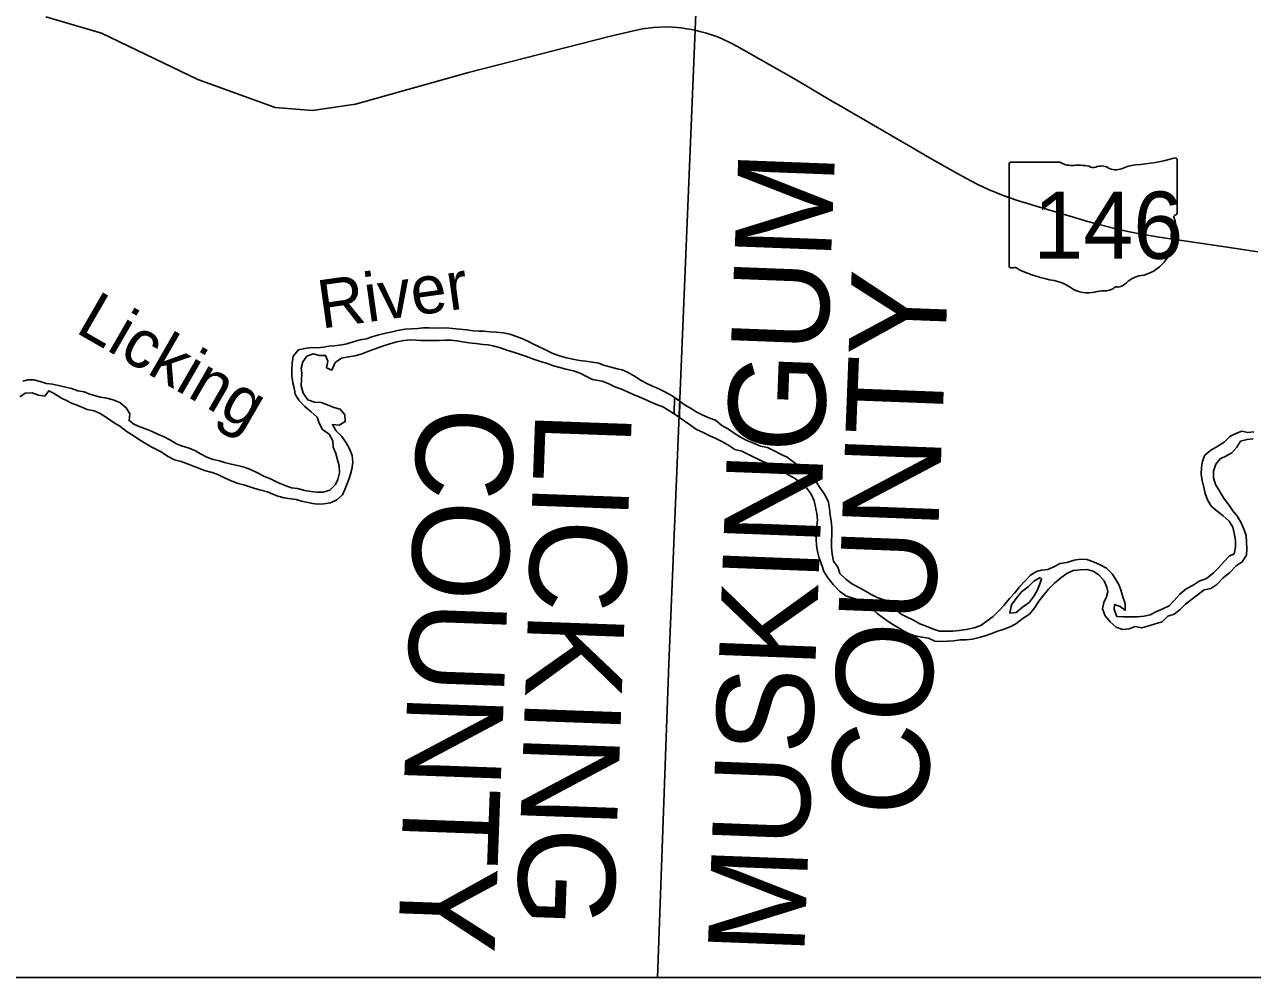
# Model space of a CAD drawing. Extents: x 0 to 34, y 0 to 22.
# Drawn here: x 13.652 to 17.715, y 13.067 to 16.221 of the extents above; entities that cross this region are included whole.
import ezdxf

# ---------------------------------------------------------------- set-up
doc = ezdxf.new("R2010")
doc.units = 0
for name, color, linetype in [('GM_X_County', 7, 'Continuous'), ('GM_X_County_Text', 7, 'Continuous'), ('GM_X_Major_River', 7, 'Continuous'), ('GM_X_Major_River_Text', 7, 'Continuous'), ('GM_X_State_Route', 7, 'Continuous'), ('GM_X_State_Shield', 7, 'Continuous'), ('SH_Text', 7, 'Continuous')]:
    doc.layers.add(name, color=color, linetype=linetype)

msp = doc.modelspace()

# ---------------------------------------------------------------- linework, layer by layer
at = {"layer": 'GM_X_County'}
msp.add_lwpolyline([(15.7461, 13.067), (15.7838, 14.1047), (15.8705, 16.2037), (15.9482, 18.1471), (15.9491, 18.1833), (15.9623, 18.562), (15.9755, 18.686), (15.9829, 18.8439), (16.0536, 20.907)], dxfattribs=at)
at = {"layer": 'GM_X_Major_River'}
for p, q in [((15.801, 14.9327), (15.8031, 14.987)), ((15.8186, 14.9217), (15.8206, 14.9754))]:
    msp.add_line(p, q, dxfattribs=at)
for points in [[(14.8859, 15.2086), (14.8681, 15.2047), (14.847, 15.2001), (14.8246, 15.1943), (14.8004, 15.1877), (14.7832, 15.1806), (14.7621, 15.1773), (14.7391, 15.1714), (14.718, 15.1643), (14.7014, 15.161), (14.6765, 15.1577), (14.6586, 15.1563), (14.6407, 15.1537), (14.6209, 15.1517), (14.6024, 15.1528), (14.5794, 15.1495), (14.5577, 15.145), (14.5405, 15.1237), (14.5368, 15.1001), (14.5362, 15.0789), (14.5363, 15.0585), (14.5396, 15.0354), (14.5442, 15.0188), (14.5475, 14.9977), (14.5591, 14.9779), (14.579, 14.9569), (14.6001, 14.9391), (14.62, 14.9213), (14.6271, 14.9015), (14.6375, 14.8804), (14.6593, 14.8658), (14.6715, 14.8435), (14.6735, 14.823), (14.6813, 14.8019), (14.6878, 14.7809), (14.693, 14.7604), (14.6943, 14.738), (14.688, 14.7149), (14.6811, 14.6989), (14.662, 14.6803), (14.6403, 14.6738), (14.6198, 14.6736), (14.6006, 14.6755), (14.5789, 14.6792), (14.5552, 14.6855), (14.5354, 14.6879), (14.5136, 14.6955), (14.4919, 14.7044), (14.4682, 14.7164), (14.4438, 14.7265), (14.4227, 14.7379), (14.3996, 14.7487), (14.3785, 14.7563), (14.3567, 14.7613), (14.3356, 14.7663), (14.3132, 14.772), (14.2972, 14.777), (14.2761, 14.782), (14.255, 14.7889), (14.2339, 14.8004), (14.2172, 14.8099), (14.1961, 14.8187), (14.1711, 14.8269), (14.1545, 14.8339), (14.1327, 14.8466), (14.1115, 14.8573), (14.0949, 14.8643), (14.0737, 14.8744), (14.052, 14.8826), (14.0334, 14.8902), (14.0136, 14.8991), (13.9975, 14.9105), (14, 14.9323), (13.9877, 14.9527), (13.9666, 14.9699), (13.9448, 14.9794), (13.9243, 14.985), (13.9026, 14.9881), (13.886, 14.9919), (13.8648, 14.9995), (13.8488, 15.0051), (13.8284, 15.0089), (13.8066, 15.0171), (13.7644, 15.0271), (13.7439, 15.0315), (13.7228, 15.0333), (13.7029, 15.0396), (13.6825, 15.0453), (13.662, 15.0452), (13.6454, 15.0406)], [(15.8206, 14.9754), (15.7932, 14.9937), (15.7708, 15.0051), (15.7509, 15.0159), (15.7298, 15.0247), (15.7132, 15.0323), (15.692, 15.0431), (15.6702, 15.0577), (15.6465, 15.0704), (15.6292, 15.078), (15.6132, 15.0817), (15.5889, 15.088), (15.5678, 15.0937), (15.5518, 15.1), (15.5307, 15.1043), (15.5083, 15.1068), (15.4878, 15.1099), (15.4661, 15.1143), (15.445, 15.118), (15.4219, 15.1249), (15.3995, 15.1325), (15.3752, 15.1445), (15.3528, 15.1559), (15.3361, 15.1635), (15.3194, 15.1724), (15.297, 15.1819), (15.2798, 15.1888), (15.2573, 15.1964), (15.2356, 15.2008), (15.2126, 15.2032), (15.1921, 15.2044), (15.1717, 15.2062), (15.155, 15.2068), (15.1371, 15.2073), (15.1141, 15.2111), (15.0917, 15.2135), (15.0694, 15.2153), (15.0476, 15.2171), (15.008, 15.2169), (14.9907, 15.2175), (14.9709, 15.218), (14.953, 15.2154), (14.9319, 15.2146), (14.9108, 15.2126), (14.8859, 15.2086)], [(14.7655, 15.1306), (14.7872, 15.139), (14.8121, 15.1481), (14.8331, 15.1553), (14.8606, 15.1644), (14.8835, 15.1709), (14.9072, 15.1755), (14.9289, 15.1775), (14.9468, 15.1763), (14.9628, 15.1751), (14.9852, 15.1752), (15.0075, 15.176), (15.0241, 15.1761), (15.0452, 15.1768), (15.0612, 15.1762), (15.0836, 15.1744), (15.1009, 15.1713), (15.122, 15.1682), (15.1444, 15.1651), (15.1693, 15.1627), (15.1859, 15.1615), (15.2019, 15.1577), (15.2262, 15.1515), (15.2474, 15.1433), (15.273, 15.1357), (15.2966, 15.1281), (15.3133, 15.1231), (15.3363, 15.1136), (15.3626, 15.1054), (15.3786, 15.1004), (15.4016, 15.0922), (15.4234, 15.0859), (15.4426, 15.0809), (15.4682, 15.0746), (15.4925, 15.0664), (15.5091, 15.0575), (15.5309, 15.0468), (15.5629, 15.0405), (15.5834, 15.0336), (15.6052, 15.0222), (15.6269, 15.0146), (15.6474, 15.0051), (15.6635, 14.9975), (15.6878, 14.988), (15.7038, 14.9811), (15.7275, 14.9703), (15.7435, 14.964), (15.764, 14.9558), (15.7839, 14.9437), (15.8186, 14.9217)], [(13.636, 14.9887), (13.6539, 15.001), (13.6763, 15.0024), (13.6974, 14.9942), (13.7185, 14.9911), (13.7318, 15.009), (13.7479, 15.0014), (13.7741, 14.9849), (13.7908, 14.9767), (13.8068, 14.9678), (13.8228, 14.9621), (13.8414, 14.9552), (13.8587, 14.947), (13.8817, 14.9426), (13.9022, 14.9337), (13.9265, 14.9185), (13.9477, 14.9026), (13.9669, 14.8918), (13.9907, 14.8727), (14.0112, 14.8607), (14.0323, 14.8467), (14.0483, 14.8372), (14.0701, 14.8232), (14.0881, 14.8144), (14.1041, 14.8074), (14.1252, 14.7928), (14.1483, 14.7807), (14.1694, 14.7751), (14.1912, 14.7675), (14.2072, 14.7605), (14.2251, 14.7542), (14.2469, 14.7454), (14.2725, 14.7385), (14.291, 14.7315), (14.3128, 14.7208), (14.3352, 14.7113), (14.3589, 14.7024), (14.3768, 14.698), (14.3967, 14.6911), (14.414, 14.6854), (14.4332, 14.6798), (14.4556, 14.6741), (14.4735, 14.6665), (14.4895, 14.6608), (14.5113, 14.6552), (14.533, 14.6515), (14.5503, 14.6496), (14.5682, 14.644), (14.5893, 14.6396), (14.6053, 14.6358), (14.6213, 14.634), (14.6417, 14.6347), (14.6641, 14.6387), (14.6851, 14.6484), (14.7042, 14.6645), (14.7118, 14.6818), (14.72, 14.7042), (14.7283, 14.7254), (14.7352, 14.7491), (14.7383, 14.7728), (14.7363, 14.7945), (14.7279, 14.815), (14.7163, 14.8373), (14.7015, 14.8583), (14.6816, 14.8781), (14.6706, 14.8972), (14.6924, 14.8954), (14.7128, 14.907), (14.712, 14.9294), (14.6966, 14.9485), (14.6755, 14.9542), (14.6537, 14.9631), (14.6332, 14.9706), (14.6115, 14.9718), (14.5891, 14.9794), (14.5737, 15.0017), (14.5672, 15.0253), (14.5677, 15.0452), (14.5689, 15.0669), (14.5675, 15.0836), (14.5726, 15.1047), (14.5859, 15.124), (14.607, 15.1311), (14.6274, 15.1261), (14.6479, 15.1262), (14.655, 15.107), (14.6513, 15.0853), (14.6686, 15.0777), (14.68, 15.1027), (14.7003, 15.1175), (14.7233, 15.1215), (14.7444, 15.1248), (14.7655, 15.1306)], [(15.8031, 14.987), (15.8382, 14.9614), (15.8581, 14.9501), (15.8747, 14.9399), (15.8946, 14.9291), (15.9164, 14.9196), (15.9388, 14.9114), (15.9593, 14.8942), (15.9811, 14.8815), (16.0003, 14.8688), (16.0208, 14.8561), (16.0425, 14.8447), (16.0643, 14.8352), (16.0874, 14.8257), (16.1104, 14.8219), (16.1322, 14.8099), (16.1533, 14.7991), (16.1751, 14.789), (16.1943, 14.775), (16.2148, 14.7591), (16.2347, 14.7457), (16.2565, 14.7266), (16.2719, 14.7075), (16.2854, 14.6858), (16.3008, 14.6641), (16.3118, 14.6405), (16.3157, 14.6181), (16.3183, 14.5989), (16.3216, 14.5772), (16.323, 14.5561), (16.3237, 14.5343), (16.3219, 14.5119), (16.3226, 14.4908), (16.324, 14.4678), (16.3286, 14.4454), (16.3433, 14.4256), (16.3498, 14.4045), (16.3691, 14.3854), (16.3889, 14.3714), (16.4101, 14.3587), (16.4312, 14.3479), (16.453, 14.3352), (16.4735, 14.3245), (16.4952, 14.3169), (16.5163, 14.3118), (16.5362, 14.2908), (16.551, 14.2704), (16.5721, 14.2596), (16.5933, 14.2495), (16.6144, 14.2374), (16.6355, 14.2298), (16.656, 14.221), (16.6797, 14.2134), (16.7014, 14.2129), (16.7232, 14.2129), (16.7449, 14.2156), (16.7679, 14.2189), (16.7947, 14.2248), (16.8164, 14.2326), (16.8374, 14.2474), (16.8572, 14.2622), (16.8769, 14.2821), (16.8922, 14.2988), (16.9112, 14.3213), (16.9284, 14.3399), (16.9443, 14.3598), (16.9628, 14.3797), (16.9806, 14.399), (17.001, 14.4106), (17.0176, 14.4158), (17.038, 14.4172), (17.0584, 14.4262), (17.0788, 14.4372), (17.1012, 14.4405), (17.1248, 14.4483), (17.1459, 14.4516), (17.1676, 14.4504), (17.1894, 14.4434), (17.2111, 14.4333), (17.2323, 14.4219), (17.2509, 14.4034), (17.2631, 14.3843), (17.2734, 14.3677), (17.2798, 14.3498), (17.2863, 14.3274), (17.2935, 14.3044), (17.2942, 14.2827), (17.2775, 14.2954), (17.2583, 14.3011), (17.2571, 14.2851), (17.2661, 14.2621), (17.2885, 14.2609), (17.3102, 14.2603), (17.3333, 14.2611), (17.3569, 14.2631), (17.3773, 14.267), (17.3977, 14.2786), (17.4188, 14.2871), (17.4392, 14.2974), (17.4557, 14.3147), (17.4735, 14.3346)], [(15.801, 14.9327), (15.8346, 14.9097), (15.8557, 14.895), (15.8756, 14.8811), (15.8974, 14.8709), (15.9192, 14.8595), (15.9396, 14.8513), (15.9588, 14.8417), (15.9793, 14.8303), (16.0018, 14.8151), (16.0254, 14.8088), (16.0479, 14.798), (16.0901, 14.7777), (16.1132, 14.7669), (16.1349, 14.7587), (16.158, 14.746), (16.1791, 14.7314), (16.1996, 14.7193), (16.2195, 14.704), (16.24, 14.6862), (16.2554, 14.6671), (16.2645, 14.6447), (16.2697, 14.6243), (16.2736, 14.6032), (16.2756, 14.5814), (16.2738, 14.561), (16.2719, 14.5386), (16.2714, 14.5187), (16.2727, 14.4983), (16.2754, 14.4771), (16.2812, 14.4548), (16.2903, 14.4318), (16.2967, 14.4107), (16.3109, 14.3884), (16.3276, 14.3673), (16.3488, 14.3457), (16.3693, 14.3304), (16.3923, 14.3228), (16.4122, 14.3171), (16.4339, 14.3057), (16.4538, 14.2905), (16.473, 14.272), (16.4935, 14.258), (16.5128, 14.2427), (16.5333, 14.2313), (16.5531, 14.2186), (16.5762, 14.2059), (16.5986, 14.1977), (16.621, 14.1933), (16.6427, 14.1902), (16.6645, 14.1807), (16.6869, 14.1795), (16.706, 14.1802), (16.7271, 14.181), (16.7476, 14.1843), (16.768, 14.185), (16.7884, 14.187), (16.8108, 14.1929), (16.8312, 14.1981), (16.8523, 14.2058), (16.8714, 14.2136), (16.8906, 14.2194), (16.9135, 14.2272), (16.9327, 14.2376), (16.9569, 14.2569), (16.9779, 14.2697), (16.9951, 14.2916), (17.0084, 14.3128), (17.0249, 14.3339), (17.0415, 14.3532), (17.0606, 14.3719), (17.0809, 14.3899), (17.1013, 14.404), (17.1224, 14.4137), (17.1447, 14.4164), (17.1671, 14.4178), (17.1876, 14.4121), (17.2074, 14.4), (17.2248, 14.3803), (17.2338, 14.3592), (17.2371, 14.3432), (17.2326, 14.3272), (17.2231, 14.3079), (17.2194, 14.2868), (17.2278, 14.2645), (17.2445, 14.2441), (17.2644, 14.2269), (17.2855, 14.2193), (17.3072, 14.2207), (17.3276, 14.2284), (17.3494, 14.2247), (17.3724, 14.2305), (17.3934, 14.2377), (17.4164, 14.2448), (17.4355, 14.2628), (17.4566, 14.2699), (17.4757, 14.2854), (17.4935, 14.3027), (17.5139, 14.3182), (17.5323, 14.333), (17.5553, 14.3504)], [(17.4735, 14.3346), (17.4958, 14.3539), (17.5188, 14.3656), (17.5392, 14.3784), (17.5634, 14.3882), (17.5864, 14.4062), (17.6042, 14.4242), (17.622, 14.4441), (17.6379, 14.4621), (17.6545, 14.4698), (17.6595, 14.4916), (17.6588, 14.5146), (17.6548, 14.5377), (17.6503, 14.5575), (17.6381, 14.5779), (17.6188, 14.5951), (17.5983, 14.6103), (17.5784, 14.6275), (17.5668, 14.648), (17.5591, 14.669), (17.5539, 14.6895), (17.5493, 14.7125), (17.546, 14.733), (17.5466, 14.756), (17.5497, 14.7759), (17.5579, 14.7957), (17.5777, 14.8125), (17.6006, 14.8254), (17.6216, 14.8395), (17.6401, 14.8575), (17.6605, 14.8672), (17.6796, 14.875), (17.6995, 14.8706), (17.7199, 14.8732)], [(17.5553, 14.3504), (17.577, 14.3549), (17.5974, 14.3678), (17.6177, 14.3884), (17.6407, 14.4077), (17.661, 14.4295), (17.6814, 14.4424), (17.696, 14.4649), (17.6972, 14.4873), (17.6959, 14.5071), (17.6945, 14.5295), (17.688, 14.5493), (17.6783, 14.5717), (17.6661, 14.5927), (17.6501, 14.6112), (17.6366, 14.6316), (17.6198, 14.6552), (17.6076, 14.6757), (17.5935, 14.6986), (17.5863, 14.721), (17.5862, 14.7434), (17.5938, 14.7658), (17.6084, 14.7838), (17.6276, 14.7922), (17.6467, 14.8032), (17.6639, 14.8224), (17.6753, 14.8423), (17.6976, 14.8482), (17.7177, 14.8502)], [(16.9121, 14.2733), (16.9338, 14.2747), (16.9548, 14.2927), (16.9758, 14.3088), (16.993, 14.33), (17.0038, 14.3505), (17.0101, 14.3665), (17.0177, 14.387), (17.0132, 14.3915)], [(17.0132, 14.3915), (16.9922, 14.3786), (16.9731, 14.3606), (16.9514, 14.3439), (16.9336, 14.322), (16.9183, 14.3008), (16.9121, 14.2733)]]:
    msp.add_lwpolyline(points, dxfattribs=at)
at = {"layer": 'GM_X_State_Route'}
for points in [[(13.7225, 16.2469), (13.9067, 16.1931), (14.2254, 16.0395), (14.4814, 15.9464), (14.6047, 15.9371), (14.7466, 15.958), (15.1209, 16.0628), (15.586, 16.1819), (15.6673, 16.2007), (15.6969, 16.2075), (15.7333, 16.2121), (15.7543, 16.2127), (15.7856, 16.2144), (15.8231, 16.2104), (15.8709, 16.2028)], [(15.8709, 16.2028), (15.8866, 16.1989), (15.9089, 16.1929), (15.9279, 16.1867), (15.9481, 16.1793), (15.9666, 16.1713), (15.9856, 16.1624), (16.0085, 16.1502), (16.0493, 16.1272), (16.2047, 16.0383), (16.326, 15.9668), (16.3625, 15.9456), (16.3713, 15.9404), (16.4351, 15.9039), (16.5348, 15.8458), (16.5982, 15.8087), (16.6389, 15.7849), (16.7346, 15.7303), (16.7806, 15.7051), (16.8087, 15.6909), (16.8419, 15.6754), (16.8659, 15.6651), (16.8904, 15.6557), (16.9349, 15.6402), (16.9964, 15.6211), (17.1077, 15.5884), (17.171, 15.57), (17.2076, 15.5599), (17.2553, 15.5473), (17.2973, 15.5378), (17.3419, 15.5289), (17.4061, 15.5177), (17.4893, 15.5052), (17.5877, 15.4916), (17.6758, 15.4784), (17.7328, 15.4695)]]:
    msp.add_lwpolyline(points, dxfattribs=at)
at = {"layer": 'GM_X_State_Shield'}
for p, q in [((17.466, 15.5974), (17.466, 15.774)), ((16.9098, 15.7598), (16.9098, 15.4221)), ((17.0781, 15.7657), (16.9153, 15.7657)), ((17.4659, 15.5974), (17.466, 15.5974))]:
    msp.add_line(p, q, dxfattribs=at)
for centre, major_axis, start_param, end_param in [((17.2678, 16.2261), (0.5898, 0), 4.814394, 5.042369), ((17.4598, 15.7748), (0.00619, 0), 6.141152, 7.989035), ((16.9162, 15.7606), (0.00644, 0), 1.712693, 3.28349), ((17.1169, 15.8049), (0.0625, 0), 4.042523, 4.731795), ((17.1376, 15.5761), (0.2244, 0), 1.404758, 1.657858), ((17.1886, 15.7623), (0.018, 0), 3.836095, 5.185415), ((17.215, 15.7233), (0.0375, 0), 0.950623, 2.079405), ((17.2634, 15.7768), (0.0451, 0), 4.081561, 5.145723), ((17.3431, 15.6625), (0.1187, 0), 1.699011, 2.107814), ((17.4645, 15.5844), (0.00958, 0), 1.883978, 3.671073), ((17.4036, 15.5621), (0.0575, 0), 5.934695, 6.695948), ((17.4593, 15.5967), (0.00663, 0), 5.05454, 6.418171), ((17.4881, 15.5234), (0.0418, 0), 2.387724, 3.262537), ((17.3009, 15.501), (0.1475, 0), 5.101752, 6.440018), ((16.9162, 15.4214), (0.0065, 0), 3.00124, 4.508301), ((16.9172, 15.456), (0.0496, 0), 4.665946, 4.897461), ((16.9273, 15.4027), (0.0179, 0), 0.519207, 1.627899), ((17.1532, 15.7061), (0.4259, 0), 4.195997, 4.488961), ((17.0262, 15.2704), (0.1333, 0), 0.823519, 1.323587), ((17.2607, 15.3894), (0.0477, 0), 4.937069, 5.64225), ((17.3631, 15.3273), (0.0808, 0), 1.647645, 2.488434), ((17.1703, 15.401), (0.0846, 0), 4.026481, 4.996735), ((17.2192, 15.2842), (0.0695, 0), 1.495662, 1.94098), ((17.2254, 15.3757), (0.0451, 0), 4.691044, 5.507374), ((17.2661, 15.343), (0.0127, 0), 1.147584, 2.315152)]:
    msp.add_ellipse(centre, major_axis=major_axis, ratio=0.8, start_param=start_param, end_param=end_param, dxfattribs=at)
at = {"layer": 'SH_Text'}
msp.add_lwpolyline([(1.9289, 20.907), (19.068, 20.907), (19.068, 13.067), (1.9289, 13.067)], close=True, dxfattribs=at)

# ---------------------------------------------------------------- texts
at = {"layer": 'GM_X_County_Text'}
for s, rotation, p in [('MUSKINGUM ', 87.7975, (16.2317, 13.1383)), ('    COUNTY', 87.7975, (16.621, 13.1233)), ('COUNTY', 267.9269, (14.9529, 14.9598)), ('LICKING ', 267.9269, (15.3423, 14.9457))]:
    msp.add_text(s, height=0.3196, rotation=rotation, dxfattribs=at).set_placement(p)
at = {"layer": 'GM_X_Major_River_Text'}
for s, height, rotation, p in [('River', 0.1598, 8.0022, (14.6337, 15.2146)), ('Licking', 0.15982, 330.0276, (13.816, 15.2049))]:
    msp.add_text(s, height=height, rotation=rotation, dxfattribs=at).set_placement(p)
at = {"layer": 'GM_X_State_Shield'}
msp.add_text('146', height=0.22247, dxfattribs=at).set_placement((16.9898, 15.446))

doc.saveas('drawing.dxf')
